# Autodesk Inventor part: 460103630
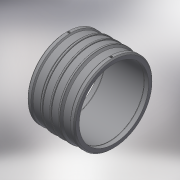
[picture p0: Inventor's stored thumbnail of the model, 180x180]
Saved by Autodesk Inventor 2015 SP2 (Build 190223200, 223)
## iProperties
Created: 2017-06
Part Number: 460103630
Material: Generic
Description: PLASSON LIGHTFIT COUPLER 630
Document SubType Name: Modeling
Designer: KIM
Mass: 33264.9 g
Surface Area: 20066.3 cm^2
Volume: 33264.9 cm^3
Density: 1 g/cm^3
Appearance: Default
Author: KIM
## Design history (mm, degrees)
derived "460103.ipt"
feature "Solid1::460103.ipt"
tag "TaggingFeature1"
body "Solid1"
other parameters: "d13" = 418, "d14" = 17.6296, "d15" = 209, "d16" = 209, "d19" = 3.52592, "d20" = 168 deg, "d22" = 712, "d23" = 726, "d24" = 690.64, "d25" = 135 deg, "d26" = 167.2, "d27" = 135 deg, "d29" = 356, "d35" = 15, "d39" = 0, "d40" = 4, "d41" = 14, "d42" = 0, "d43" = 135 deg, "d44" = 45.98, "d45" = 16.72, "d46" = 16.72, "d47" = 16.72, "d48" = 711.48, "d49" = 726, "d50" = 3.63, "d51" = 6, "d52" = 0, "L_" = 418, "L_1" = 209, "D_" = 726, "A_" = 356, "d_2" = 12
